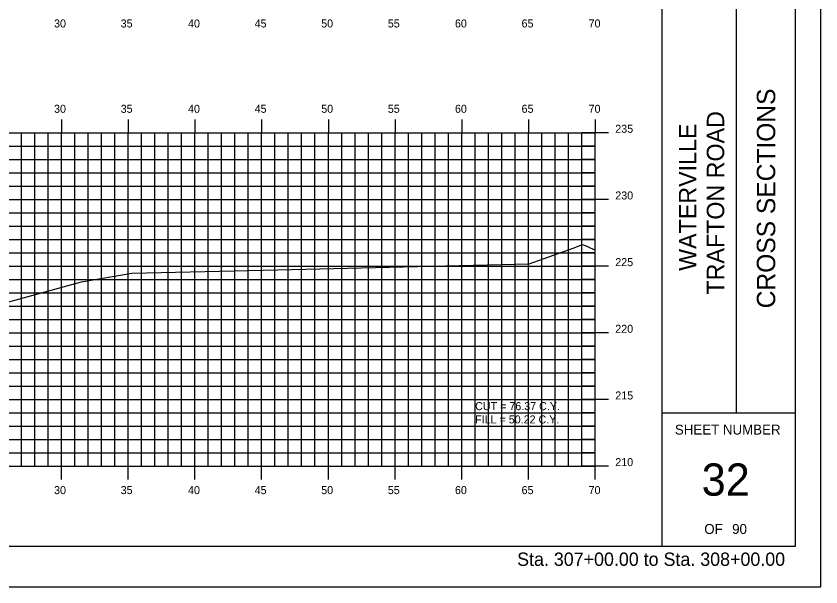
# Model space of a CAD drawing. Extents: x 1137654 to 1137824, y 608981 to 609091.
# Drawn here: x 1137764 to 1137824.3, y 608981.3 to 609024.1 of the extents above; entities that cross this region are included whole.
import ezdxf

# ---------------------------------------------------------------- set-up
doc = ezdxf.new("R2010")
doc.units = 0
for name, color, linetype in [('BORDER', 7, 'Continuous'), ('D_Text_Standard', 7, 'Continuous'), ('H_V ANNOTATION', 7, 'Continuous'), ('HIGHWAY_TITLE', 7, 'Continuous'), ('MAJOR', 7, 'Continuous'), ('MINOR', 7, 'Continuous'), ('PLOT BOUNDARY', 7, 'Continuous'), ('S_Roadway_Centerline', 7, 'Continuous')]:
    doc.layers.add(name, color=color, linetype=linetype)

msp = doc.modelspace()

# ---------------------------------------------------------------- linework, layer by layer
at = {"layer": 'BORDER'}
for p, q in [((1137812.41, 608984.335), (1137812.41, 609089.335)), ((1137818.001, 608994.338), (1137818.001, 609029.338)), ((1137812.41, 608994.338), (1137822.41, 608994.338))]:
    msp.add_line(p, q, dxfattribs=at)
msp.add_lwpolyline([(1137662.41, 608984.335), (1137822.41, 608984.335), (1137822.41, 609089.335), (1137662.41, 609089.335)], close=True, dxfattribs=at)
at = {"layer": 'MAJOR'}
for p, q in [((1137767.409, 609016.337), (1137767.409, 609015.335)), ((1137772.409, 609016.337), (1137772.409, 609015.335)), ((1137777.409, 609016.337), (1137777.409, 609015.335)), ((1137782.409, 609016.337), (1137782.409, 609015.335)), ((1137787.409, 609016.337), (1137787.409, 609015.335)), ((1137792.409, 609016.337), (1137792.409, 609015.335)), ((1137797.409, 609016.337), (1137797.409, 609015.335)), ((1137802.409, 609016.337), (1137802.409, 609015.335)), ((1137807.409, 609016.337), (1137807.409, 609015.335)), ((1137667.409, 609015.335), (1137807.409, 609015.335)), ((1137667.409, 609015.335), (1137807.409, 609015.335)), ((1137767.409, 608990.335), (1137767.409, 609015.335)), ((1137772.409, 608990.335), (1137772.409, 609015.335)), ((1137777.409, 608990.335), (1137777.409, 609015.335)), ((1137782.409, 608990.335), (1137782.409, 609015.335)), ((1137787.409, 608990.335), (1137787.409, 609015.335)), ((1137792.409, 608990.335), (1137792.409, 609015.335)), ((1137797.409, 608990.335), (1137797.409, 609015.335)), ((1137802.409, 608990.335), (1137802.409, 609015.335)), ((1137808.411, 609015.335), (1137806.407, 609015.335)), ((1137807.409, 608990.335), (1137807.409, 609015.335)), ((1137807.409, 608990.335), (1137807.409, 609015.335)), ((1137667.409, 609010.335), (1137807.409, 609010.335)), ((1137808.411, 609010.335), (1137806.407, 609010.335)), ((1137667.409, 609005.335), (1137807.409, 609005.335)), ((1137808.411, 609005.335), (1137806.407, 609005.335)), ((1137667.409, 609000.335), (1137807.409, 609000.335)), ((1137808.411, 609000.335), (1137806.407, 609000.335)), ((1137667.409, 608995.335), (1137807.409, 608995.335)), ((1137808.411, 608995.335), (1137806.407, 608995.335)), ((1137667.409, 608990.335), (1137807.409, 608990.335)), ((1137667.409, 608990.335), (1137807.409, 608990.335)), ((1137767.409, 608989.333), (1137767.409, 608990.335)), ((1137772.409, 608989.333), (1137772.409, 608990.335)), ((1137777.409, 608989.333), (1137777.409, 608990.335)), ((1137782.409, 608989.333), (1137782.409, 608990.335)), ((1137787.409, 608989.333), (1137787.409, 608990.335)), ((1137792.409, 608989.333), (1137792.409, 608990.335)), ((1137797.409, 608989.333), (1137797.409, 608990.335)), ((1137802.409, 608989.333), (1137802.409, 608990.335)), ((1137808.411, 608990.335), (1137806.407, 608990.335)), ((1137807.409, 608989.333), (1137807.409, 608990.335))]:
    msp.add_line(p, q, dxfattribs=at)
at = {"layer": 'MINOR'}
for p, q in [((1137764.409, 608990.335), (1137764.409, 609015.335)), ((1137765.409, 608990.335), (1137765.409, 609015.335)), ((1137766.409, 608990.335), (1137766.409, 609015.335)), ((1137768.409, 608990.335), (1137768.409, 609015.335)), ((1137769.409, 608990.335), (1137769.409, 609015.335)), ((1137770.409, 608990.335), (1137770.409, 609015.335)), ((1137771.409, 608990.335), (1137771.409, 609015.335)), ((1137773.409, 608990.335), (1137773.409, 609015.335)), ((1137774.409, 608990.335), (1137774.409, 609015.335)), ((1137775.409, 608990.335), (1137775.409, 609015.335)), ((1137776.409, 608990.335), (1137776.409, 609015.335)), ((1137778.409, 608990.335), (1137778.409, 609015.335)), ((1137779.409, 608990.335), (1137779.409, 609015.335)), ((1137780.409, 608990.335), (1137780.409, 609015.335)), ((1137781.409, 608990.335), (1137781.409, 609015.335)), ((1137783.409, 608990.335), (1137783.409, 609015.335)), ((1137784.409, 608990.335), (1137784.409, 609015.335)), ((1137785.409, 608990.335), (1137785.409, 609015.335)), ((1137786.409, 608990.335), (1137786.409, 609015.335)), ((1137788.409, 608990.335), (1137788.409, 609015.335)), ((1137789.409, 608990.335), (1137789.409, 609015.335)), ((1137790.409, 608990.335), (1137790.409, 609015.335)), ((1137791.409, 608990.335), (1137791.409, 609015.335)), ((1137793.409, 608990.335), (1137793.409, 609015.335)), ((1137794.409, 608990.335), (1137794.409, 609015.335)), ((1137795.409, 608990.335), (1137795.409, 609015.335)), ((1137796.409, 608990.335), (1137796.409, 609015.335)), ((1137798.409, 608990.335), (1137798.409, 609015.335)), ((1137799.409, 608990.335), (1137799.409, 609015.335)), ((1137800.409, 608990.335), (1137800.409, 609015.335)), ((1137801.409, 608990.335), (1137801.409, 609015.335)), ((1137803.409, 608990.335), (1137803.409, 609015.335)), ((1137804.409, 608990.335), (1137804.409, 609015.335)), ((1137805.409, 608990.335), (1137805.409, 609015.335)), ((1137806.409, 608990.335), (1137806.409, 609015.335)), ((1137667.409, 609014.335), (1137807.409, 609014.335)), ((1137807.409, 609014.335), (1137806.407, 609014.335)), ((1137667.409, 609013.335), (1137807.409, 609013.335)), ((1137807.409, 609013.335), (1137806.407, 609013.335)), ((1137667.409, 609012.335), (1137807.409, 609012.335)), ((1137807.409, 609012.335), (1137806.407, 609012.335)), ((1137667.409, 609011.335), (1137807.409, 609011.335)), ((1137807.409, 609011.335), (1137806.407, 609011.335)), ((1137667.409, 609009.335), (1137807.409, 609009.335)), ((1137807.409, 609009.335), (1137806.407, 609009.335)), ((1137667.409, 609008.335), (1137807.409, 609008.335)), ((1137807.409, 609008.335), (1137806.407, 609008.335)), ((1137667.409, 609007.335), (1137807.409, 609007.335)), ((1137807.409, 609007.335), (1137806.407, 609007.335)), ((1137667.409, 609006.335), (1137807.409, 609006.335)), ((1137807.409, 609006.335), (1137806.407, 609006.335)), ((1137667.409, 609004.335), (1137807.409, 609004.335)), ((1137807.409, 609004.335), (1137806.407, 609004.335)), ((1137667.409, 609003.335), (1137807.409, 609003.335)), ((1137807.409, 609003.335), (1137806.407, 609003.335)), ((1137667.409, 609002.335), (1137807.409, 609002.335)), ((1137807.409, 609002.335), (1137806.407, 609002.335)), ((1137667.409, 609001.335), (1137807.409, 609001.335)), ((1137807.409, 609001.335), (1137806.407, 609001.335)), ((1137667.409, 608999.335), (1137807.409, 608999.335)), ((1137807.409, 608999.335), (1137806.407, 608999.335)), ((1137667.409, 608998.335), (1137807.409, 608998.335)), ((1137807.409, 608998.335), (1137806.407, 608998.335)), ((1137667.409, 608997.335), (1137807.409, 608997.335)), ((1137807.409, 608997.335), (1137806.407, 608997.335)), ((1137667.409, 608996.335), (1137807.409, 608996.335)), ((1137807.409, 608996.335), (1137806.407, 608996.335)), ((1137667.409, 608994.335), (1137807.409, 608994.335)), ((1137807.409, 608994.335), (1137806.407, 608994.335)), ((1137667.409, 608993.335), (1137807.409, 608993.335)), ((1137807.409, 608993.335), (1137806.407, 608993.335)), ((1137667.409, 608992.335), (1137807.409, 608992.335)), ((1137807.409, 608992.335), (1137806.407, 608992.335)), ((1137667.409, 608991.335), (1137807.409, 608991.335)), ((1137807.409, 608991.335), (1137806.407, 608991.335))]:
    msp.add_line(p, q, dxfattribs=at)
at = {"layer": 'PLOT BOUNDARY'}
msp.add_lwpolyline([(1137654.316, 608981.276), (1137824.316, 608981.276), (1137824.316, 609091.276), (1137654.316, 609091.276)], close=True, dxfattribs=at)
at = {"layer": 'S_Roadway_Centerline'}
msp.add_lwpolyline([(1137762.91, 609002.502), (1137768.911, 609004.157), (1137772.688, 609004.799), (1137783.616, 609005.068), (1137802.452, 609005.501), (1137805.758, 609006.693), (1137806.441, 609006.957), (1137806.778, 609006.842), (1137807.409, 609006.52)], dxfattribs=at)

# ---------------------------------------------------------------- texts
at = {"layer": 'BORDER'}
msp.add_text('CROSS SECTIONS', height=1.37787, rotation=90, dxfattribs=at).set_placement((1137820.894, 609002.172))
for s, height, p in [('SHEET NUMBER', 0.74527, (1137813.375, 608992.701)), ('32', 2.4194, (1137815.385, 608988.118)), ('OF', 0.7453, (1137815.577, 608985.248)), ('90', 0.7453, (1137817.666, 608985.248))]:
    msp.add_text(s, height=height, dxfattribs=at).set_placement(p)
at = {"layer": 'D_Text_Standard'}
for s, p in [('CUT = 76.37 C.Y.', (1137798.409, 608994.535)), ('FILL = 50.22 C.Y.', (1137798.409, 608993.539))]:
    msp.add_text(s, height=0.6, dxfattribs=at).set_placement(p)
at = {"layer": 'H_V ANNOTATION'}
for s, height, p in [('30', 0.6, (1137766.858, 609023.235)), ('35', 0.6, (1137771.85, 609023.235)), ('40', 0.6, (1137776.896, 609023.235)), ('45', 0.6, (1137781.888, 609023.235)), ('50', 0.6, (1137786.874, 609023.235)), ('55', 0.6, (1137791.866, 609023.235)), ('60', 0.6, (1137796.896, 609023.235)), ('65', 0.6, (1137801.888, 609023.235)), ('70', 0.6, (1137806.911, 609023.235)), ('30', 0.6, (1137766.858, 609016.835)), ('35', 0.6, (1137771.85, 609016.835)), ('40', 0.6, (1137776.896, 609016.835)), ('45', 0.6, (1137781.888, 609016.835)), ('50', 0.6, (1137786.874, 609016.835)), ('55', 0.6, (1137791.866, 609016.835)), ('60', 0.6, (1137796.896, 609016.835)), ('65', 0.6, (1137801.888, 609016.835)), ('70', 0.6, (1137806.911, 609016.835)), ('235', 0.6, (1137808.909, 609015.335)), ('230', 0.6, (1137808.909, 609010.335)), ('225', 0.6, (1137808.909, 609005.335)), ('220', 0.6, (1137808.909, 609000.335)), ('215', 0.6, (1137808.909, 608995.335)), ('210', 0.6, (1137808.909, 608990.335)), ('30', 0.6, (1137766.858, 608988.235)), ('35', 0.6, (1137771.85, 608988.235)), ('40', 0.6, (1137776.896, 608988.235)), ('45', 0.6, (1137781.888, 608988.235)), ('50', 0.6, (1137786.874, 608988.235)), ('55', 0.6, (1137791.866, 608988.235)), ('60', 0.6, (1137796.896, 608988.235)), ('65', 0.6, (1137801.888, 608988.235)), ('70', 0.6, (1137806.911, 608988.235)), ('Sta. 307+00.00 to Sta. 308+00.00', 1.0002, (1137801.555, 608982.855))]:
    msp.add_text(s, height=height, dxfattribs=at).set_placement(p)
at = {"layer": 'HIGHWAY_TITLE'}
for s, height, p in [('TRAFTON ROAD', 1.30428, (1137817.069, 609003.201)), ('WATERVILLE', 1.3043, (1137814.982, 609004.98))]:
    msp.add_text(s, height=height, rotation=90, dxfattribs=at).set_placement(p)

doc.saveas('drawing.dxf')
